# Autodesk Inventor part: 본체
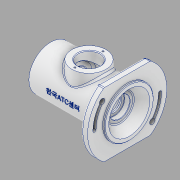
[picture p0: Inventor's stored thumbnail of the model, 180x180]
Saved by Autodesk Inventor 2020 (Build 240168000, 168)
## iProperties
Created: 2022-05
Part Number: 본체
Material: 알루미늄 6061
Document SubType Name: Modeling
Designer: Student
Density: 2.7 g/cm^3
Appearance: 알루미늄 - 평지
Mass: 691.495 g
Surface Area: 623.5 cm^2
Volume: 256.109 cm^3
Author: Student
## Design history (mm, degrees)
sketch "스케치2"
  geometry: L1 (47, 33.985)-(47, -33.985); L2 (-47, 33.985)-(-47, -33.985); A1 r 58 centre (0, 0) between (47, 33.985) and (-47, 33.985); A2 r 58 centre (0, 0) between (-47, -33.985) and (47, -33.985); 5 further points
  constraints: 6 point on circle, 4 end point, 2 centre point, 2 horizontal alignment, 2 midpoint, 2 vertical, 2 vertical alignment, 1 coincident
  dimensions: "d0" = 58 radius of A1; "d1" = 94 distance between parallel lines of L2 L1
extrude "돌출1" new body sketch "스케치2" distance "d2" = 10; taper "d3" = 0 deg
sketch "스케치3"
  geometry: C1 r 36 at (0, 0); 1 further point
  constraints: 1 centre point, 1 coincident
  dimensions: "d4" = 72 diameter of C1
extrude "돌출2" join sketch "스케치3" distance "d5" = 3; taper "d6" = 0 deg
sketch "스케치4"
  geometry: C1 r 32 at (0, 0); 1 further point
  constraints: 1 centre point, 1 coincident
  dimensions: "d7" = 64 diameter of C1
extrude "돌출3" join sketch "스케치4" distance "d8" = 102; taper "d9" = 0 deg
sketch "스케치5"
  geometry: L1 (13, -36)-(13, 36) reference; L2 (-9, 11)-(-11, 11); L3 (-11, 11)-(-11, 15); L4 (-11, 15)-(-16, 15); L5 (-16, 15)-(-16, 17.5); L6 (-16, 17.5)-(-27, 17.5); L7 (-27, 17.5)-(-27, 27); L8 (-27, 27)-(-65, 27); L9 (10, -47)-(10, 47) reference; L10 (-133.779, 0)-(159.779, 0); L11 (13, 30)-(13, 0); L12 (13, 30)-(-1, 20); L13 (-1, 20)-(-1, 15.404); L14 (0, -47)-(0, 47) reference; L15 (-9, 11)-(-9, 15); L16 (-9, 15)-(-1.7, 15); L17 (-1.7, 15)-(-1, 15.404); L18 (-102, 32)-(-102, -32) reference; L19 (-65, 27)-(-65, 17.5); L20 (-65, 17.5)-(-76, 17.5); L21 (-76, 17.5)-(-76, 18.5); L22 (-76, 18.5)-(-77.75, 18.5); L23 (-77.75, 18.5)-(-77.75, 17.5); L24 (-77.75, 17.5)-(-80, 17.5); L25 (-80, 17.5)-(-80, 22.5); L26 (-80, 22.5)-(-91, 22.5); L27 (-91, 22.5)-(-91, 24); L28 (-91, 24)-(-94, 24); L29 (-94, 24)-(-94, 0); L30 (13, 0)-(-94, 0); 2 further points
  constraints: 52 end point, 13 perpendicular, 5 horizontal, 3 vertical, 2 midpoint, 2 point on line, 1 coincident, 1 collinear, 1 parallel
  dimensions: "d10" = 60 diameter of L11.start L10; "d11" = 40 diameter of L12.end L10; "d12" = 22 diameter of L2 L10; "d13" = 14 distance between parallel lines of L1 L13; "d14" = 30 deg angle of L16 L17; "d15" = 0.7 horizontal distance of L13.end L16.end; "d16" = 7.3 distance of L15.end L16.end; "d17" = 30 diameter of L16 L10; "d18" = 5 distance of L3.end L4.end; "d19" = 29 distance from line of L1 L4.end; "d20" = 54 diameter of L8 L10; "d21" = 30 diameter of L4 L10; "d22" = 35 diameter of L6 L10; "d23" = 11 distance of L5.end L6.end; "d24" = 38 distance of L7.end L8.end; "d47" = 35 diameter of L20 L10; "d48" = 11 distance of L19.end L20.end; "d51" = 1.75 distance of L21.end L22.end; "d52" = 37 diameter of L22 L10; "d53" = 4 horizontal distance of L21.end L24.end; "d54" = 35 diameter of L24 L10; "d55" = 45 diameter of L26 L10; "d56" = 48 diameter of L28 L10; "d58" = 8 distance between parallel lines of L18 L29; "d59" = 3 distance of L27.end L28.end
revolve "회전1" sketch "스케치5" stored, may be unused: angle "d60" = 90 deg
sketch "스케치6"
  geometry: 2 further points
  constraints: 1 coincident
hole "구멍1" sketch "스케치6" at (0, 0) diameter "d61" = 43.376; stored, may be unused: countersink angle "d65" = 90 deg, drill point angle "d67" = 0 deg; dims "d62" = 8, "d63" = 4, "d64" = 2, "d66" = 10
chamfer "모따기1" distance "d68" = 1; stored, may be unused: second distance "d69" = 2, angle "d70" = 45 deg
chamfer "모따기2" distance "d71" = 1; stored, may be unused: second distance "d72" = 2, angle "d73" = 45 deg
chamfer "모따기3" distance "d74" = 1; stored, may be unused: second distance "d75" = 2, angle "d76" = 45 deg
fillet "모깎기1" dims "d77" = 3
fillet "모깎기2" dims "d78" = 0.5
fillet "모깎기3" dims "d79" = 0.6
sketch "스케치10"
  geometry: L1 (0, 0)-(-36.77, 30.854); L2 (-61.812, 0)-(67.211, 0); L3 (36.77, -30.854)-(0, 0); A1 r 48 centre (0, 0) between (-36.77, 30.854) and (36.77, -30.854); A2 r 48 centre (0, 0) between (-36.77, 30.854) and (-48, 0); A3 r 50.25 centre (0, 0) between (-38.494, 32.3) and (-50.25, 0); A4 r 45.75 centre (0, 0) between (-35.047, 29.408) and (-45.75, 0); A5 r 2.25 centre (-36.77, 30.854) between (-35.047, 29.408) and (-38.494, 32.3); A6 r 2.25 centre (-48, 0) between (-50.25, 0) and (-45.75, 0); A7 r 48 centre (0, 0) between (36.77, -30.854) and (48, 0); A8 r 50.25 centre (0, 0) between (38.494, -32.3) and (50.25, 0); A9 r 45.75 centre (0, 0) between (35.047, -29.408) and (45.75, 0); A10 r 2.25 centre (36.77, -30.854) between (35.047, -29.408) and (38.494, -32.3); A11 r 2.25 centre (48, 0) between (50.25, 0) and (45.75, 0); 1 further point
  constraints: 22 point on circle, 11 centre point, 8 tangent, 6 end point, 3 coincident, 2 horizontal alignment, 1 concentric, 1 horizontal
  dimensions: "d99" = 96 diameter of A1; "d100" = 4.5 diameter of A6; "d101" = 40 deg angle of L2 L1; "d102" = 4.5 diameter of A11; "d103" = 40 deg angle of L3 L2
extrude "돌출6" cut sketch "스케치10" distance "d104" = 5.6; taper "d105" = 0 deg
sketch "스케치11"
  geometry: A1 r 2.25 centre (-36.77, 30.854) between (-35.047, 29.408) and (-38.494, 32.3) reference; A2 r 50.25 centre (0, 0) between (-38.494, 32.3) and (-50.25, 0) reference; A3 r 2.25 centre (-48, 0) between (-50.25, 0) and (-45.75, 0) reference; A4 r 45.75 centre (0, 0) between (-35.047, 29.408) and (-45.75, 0) reference; A5 r 50.25 centre (0, 0) between (38.494, -32.3) and (50.25, 0) reference; A6 r 2.25 centre (48, 0) between (50.25, 0) and (45.75, 0) reference; A7 r 45.75 centre (0, 0) between (35.047, -29.408) and (45.75, 0) reference; A8 r 2.25 centre (36.77, -30.854) between (35.047, -29.408) and (38.494, -32.3) reference; A9 r 48 centre (0, 0) between (-36.77, 30.854) and (-48, 0); A10 r 52 centre (0, 0) between (-39.834, 33.425) and (-52, 0); A11 r 44 centre (0, 0) between (-33.706, 28.283) and (-44, 0); A12 r 4 centre (-36.77, 30.854) between (-33.706, 28.283) and (-39.834, 33.425); A13 r 4 centre (-48, 0) between (-52, 0) and (-44, 0); A14 r 48 centre (0, 0) between (36.77, -30.854) and (48, 0); A15 r 52 centre (0, 0) between (39.834, -33.425) and (52, 0); A16 r 44 centre (0, 0) between (33.706, -28.283) and (44, 0); A17 r 4 centre (36.77, -30.854) between (33.706, -28.283) and (39.834, -33.425); A18 r 4 centre (48, 0) between (52, 0) and (44, 0); 1 further point
  constraints: 20 point on circle, 10 centre point, 8 tangent, 2 coincident, 1 concentric
  dimensions: "d106" = 8 diameter of A12; "d107" = 8 diameter of A17 (derived)
extrude "돌출7" cut sketch "스케치11" distance "d108" = 4.4; taper "d109" = 0 deg
sketch "스케치12"
  geometry: A1 r 2.25 centre (-36.77, 30.854) between (-35.047, 29.408) and (-38.494, 32.3) reference; A2 r 2.25 centre (48, 0) between (50.25, 0) and (45.75, 0) reference; A3 r 2.25 centre (36.77, -30.854) between (35.047, -29.408) and (38.494, -32.3) reference; 1 further point
hole "구멍3" sketch "스케치12" at (-36.77, 30.854), (36.77, -30.854) diameter "d110" = 8; stored, may be unused: countersink angle "d114" = 90 deg, drill point angle "d116" = 0 deg; dims "d111" = 8, "d112" = 4, "d113" = 2, "d115" = 10
node "작업 평면1"
sketch "스케치13"
  geometry: L1 (102, -32)-(102, 32) reference; L2 (-10, -33.985)-(-10, 33.985) reference; C1 r 25 at (46, 0); 2 further points
  constraints: 1 centre point, 1 horizontal alignment, 1 midpoint
  dimensions: "d118" = 50 diameter of C1; "d119" = 56 distance from line of L1 C1.centre
extrude "돌출8" join sketch "스케치13" stored distance "d120" = 4.4; taper "d121" = 5 deg
sketch "스케치14"
  geometry: C1 r 25 at (0, 0) reference; 1 further point
hole "구멍4" sketch "스케치14" at (0, 0) diameter "d122" = 32; stored, may be unused: countersink angle "d126" = 90 deg, drill point angle "d128" = 0 deg; dims "d123" = 8, "d124" = 4, "d125" = 2, "d127" = 35
sketch "스케치15"
  geometry: A1 r 20.5 centre (0, 0) between (0, 20.5) and (0, -20.5); 1 further point
  constraints: 2 point on circle, 1 centre point, 1 vertical alignment
  dimensions: "d129" = 41 diameter of A1; "d130" = 50.3612 distance of point (46, 0) A1.start; "d131" = 46 distance of point (46, 0) A1.centre; "d132" = 50.3612 distance of point (46, 0) A1.end
hole "구멍5" sketch "스케치15" at (0, 20.5), (0, -20.5) diameter "d133" = 2.459; stored, may be unused: countersink angle "d137" = 90 deg, drill point angle "d139" = 118 deg; dims "d134" = 6, "d135" = 4, "d136" = 2, "d138" = 8
node "작업 평면2"
sketch "스케치16"
  geometry: L1 (-80.339, 10.962)-(-23.661, 10.962); L2 (-23.661, 10.962)-(-23.661, -10.962); L3 (-23.661, -10.962)-(-80.339, -10.962); L4 (-80.339, -10.962)-(-80.339, 10.962); L5 (-23.661, 0)-(-80.339, 0); L6 (-52, 10.962)-(-52, -10.962); L7 (10, -47)-(10, 47) reference; L8 (10, 0)-(4.4, 0) reference; 3 further points
  constraints: 6 midpoint, 4 end point, 1 horizontal alignment, 2 other
  dimensions: "d141" = 62 distance between parallel lines of L7 L6
feature "엠보싱1" sketch "스케치16" dims "d0" = 58, "d1" = 94, "d142" = 0.5, "d143" = 0
chamfer "모따기4" distance "d144" = 1; stored, may be unused: second distance "d145" = 2, angle "d146" = 45 deg
fillet "모깎기4" dims "d147" = 3
fillet "모깎기5" dims "d148" = 3
fillet "모깎기6" dims "d149" = 3
chamfer "모따기5" distance "d150" = 1; stored, may be unused: second distance "d151" = 2, angle "d152" = 45 deg
chamfer "모따기6" distance "d153" = 1; stored, may be unused: second distance "d154" = 2, angle "d155" = 45 deg
node "솔리드1"
node "투영된 루프2"
node "투영된 루프3"
feature "A9D066F2-1C7D-4E18-AEED-F7BC21143FA4" dims "d61" = 43.376, "d62" = 8, "d63" = 4, "d64" = 2, "d65" = 90 deg, "d66" = 10, "d67" = 0
other parameters: "d117" = 38
